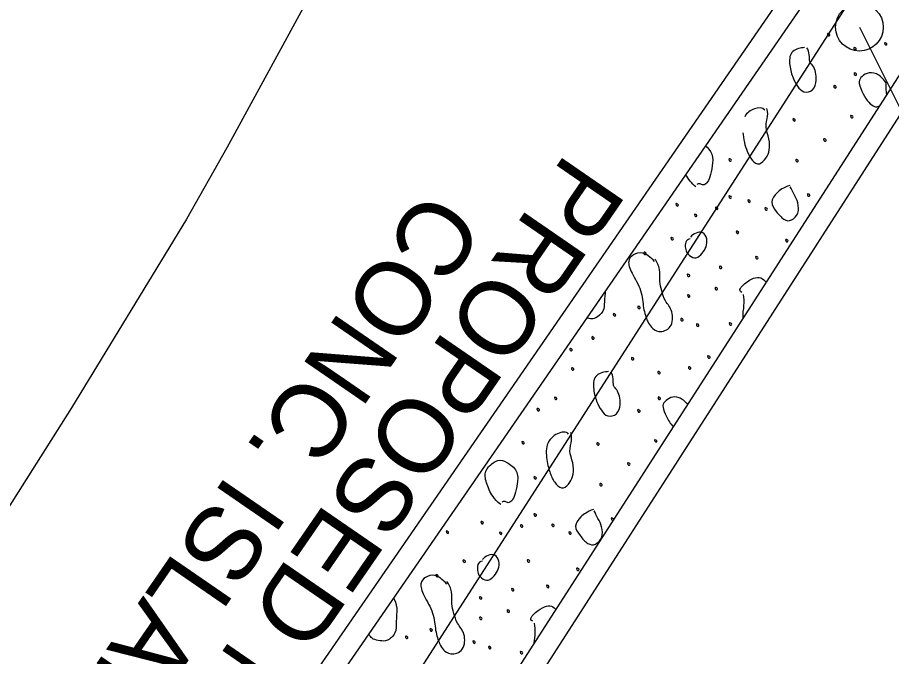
# Model space of a CAD drawing. Extents: x 1763480 to 1764420, y 711010 to 712012.
# Drawn here: x 1763800.78 to 1763830.2, y 711388.07 to 711409.59 of the extents above; entities that cross this region are included whole.
import ezdxf

# ---------------------------------------------------------------- set-up
doc = ezdxf.new("R2010")
doc.units = 0
for name, color, linetype in [('Old_Level_10', 7, 'Continuous'), ('Prop Conc Island Cover', 7, 'Continuous'), ('Prop EOT', 7, 'Continuous'), ('Prop Grid Mask', 7, 'Continuous'), ('Prop Lane Lines', 7, 'Continuous'), ('Sheet Block Revision CELL', 7, 'Continuous')]:
    doc.layers.add(name, color=color, linetype=linetype)

msp = doc.modelspace()

# ---------------------------------------------------------------- linework, layer by layer
at = {"layer": 'Old_Level_10'}
for points in [[(1763828.07, 711409.063), (1763828.044, 711409.064), (1763828.04, 711408.985), (1763828.119, 711408.957), (1763828.139, 711409.021), (1763828.104, 711409.042), (1763828.081, 711409.052), (1763828.069, 711409.056)], [(1763829.989, 711408.755), (1763829.963, 711408.755), (1763829.961, 711408.68), (1763830.039, 711408.652), (1763830.058, 711408.711), (1763830.024, 711408.736), (1763830.001, 711408.745), (1763829.988, 711408.748)], [(1763827.273, 711408.581), (1763827.161, 711408.572), (1763826.802, 711408.51), (1763826.742, 711408.056), (1763826.87, 711407.553), (1763827.038, 711407.269), (1763827.226, 711407.043), (1763827.592, 711407.107), (1763827.688, 711407.49), (1763827.655, 711407.758), (1763827.567, 711407.985), (1763827.422, 711408.088), (1763827.456, 711408.339), (1763827.396, 711408.509), (1763827.358, 711408.573)], [(1763828.956, 711408.599), (1763828.93, 711408.598), (1763828.927, 711408.524), (1763829.005, 711408.491), (1763829.025, 711408.554), (1763828.99, 711408.578), (1763828.967, 711408.587), (1763828.955, 711408.59)], [(1763828.967, 711407.735), (1763828.94, 711407.735), (1763828.937, 711407.657), (1763829.017, 711407.63), (1763829.036, 711407.692), (1763829.001, 711407.715), (1763828.978, 711407.724), (1763828.966, 711407.727)], [(1763830.021, 711407.394), (1763829.914, 711407.538), (1763829.693, 711407.748), (1763829.366, 711407.733), (1763829.154, 711407.568), (1763829.076, 711407.407), (1763829.254, 711407.007), (1763829.429, 711406.712), (1763829.649, 711406.573), (1763829.722, 711406.584), (1763829.796, 711406.613)], [(1763828.282, 711407.309), (1763828.256, 711407.309), (1763828.253, 711407.232), (1763828.332, 711407.202), (1763828.352, 711407.264), (1763828.317, 711407.288), (1763828.294, 711407.296), (1763828.281, 711407.3)], [(1763830.048, 711407.005), (1763830.035, 711407.063), (1763830.021, 711407.194), (1763830.017, 711407.323), (1763830.021, 711407.394)], [(1763825.203, 711405.711), (1763825.211, 711405.641), (1763825.241, 711405.36), (1763825.338, 711405.1), (1763825.495, 711404.754), (1763825.76, 711404.601), (1763825.997, 711404.858), (1763826.107, 711405.104), (1763826.103, 711405.512), (1763825.927, 711405.908), (1763826.069, 711406.272), (1763826.019, 711406.486), (1763826.004, 711406.529)], [(1763825.935, 711406.474), (1763825.86, 711406.566), (1763825.576, 711406.553), (1763825.332, 711406.386), (1763825.264, 711406.251)], [(1763826.905, 711406.196), (1763826.879, 711406.196), (1763826.876, 711406.119), (1763826.955, 711406.089), (1763826.975, 711406.151), (1763826.939, 711406.175), (1763826.917, 711406.184), (1763826.904, 711406.187)], [(1763828.848, 711406.299), (1763828.822, 711406.298), (1763828.82, 711406.224), (1763828.896, 711406.193), (1763828.918, 711406.254), (1763828.882, 711406.278), (1763828.86, 711406.287), (1763828.847, 711406.29)], [(1763827.942, 711405.517), (1763827.916, 711405.517), (1763827.912, 711405.44), (1763827.992, 711405.41), (1763828.012, 711405.473), (1763827.976, 711405.496), (1763827.954, 711405.504), (1763827.941, 711405.508)], [(1763823.94, 711405.272), (1763824.005, 711405.231), (1763824.206, 711404.993), (1763824.175, 711404.594), (1763824.092, 711404.192), (1763823.986, 711403.999), (1763823.859, 711403.926), (1763823.765, 711404.012), (1763823.672, 711403.989), (1763823.644, 711403.971)], [(1763824.751, 711404.841), (1763824.725, 711404.841), (1763824.722, 711404.763), (1763824.8, 711404.736), (1763824.822, 711404.798), (1763824.786, 711404.821), (1763824.764, 711404.83), (1763824.751, 711404.833)], [(1763827.003, 711404.822), (1763826.977, 711404.823), (1763826.974, 711404.745), (1763827.053, 711404.715), (1763827.073, 711404.779), (1763827.037, 711404.801), (1763827.015, 711404.81), (1763827.002, 711404.814)], [(1763823.613, 711403.887), (1763823.474, 711404.006), (1763823.361, 711404.153), (1763823.273, 711404.305)], [(1763826.777, 711403.938), (1763826.555, 711403.859), (1763826.333, 711403.703), (1763826.096, 711403.374), (1763826.313, 711403.054), (1763826.587, 711402.749), (1763826.833, 711402.726), (1763827.097, 711402.984), (1763827.067, 711403.366), (1763826.922, 711403.638), (1763826.833, 711403.811), (1763826.793, 711403.894)], [(1763824.753, 711403.592), (1763824.727, 711403.592), (1763824.724, 711403.513), (1763824.802, 711403.486), (1763824.824, 711403.548), (1763824.788, 711403.57), (1763824.765, 711403.579), (1763824.752, 711403.583)], [(1763825.388, 711403.457), (1763825.362, 711403.457), (1763825.358, 711403.381), (1763825.437, 711403.351), (1763825.458, 711403.415), (1763825.423, 711403.437), (1763825.4, 711403.446), (1763825.387, 711403.45)], [(1763827.393, 711403.66), (1763827.367, 711403.661), (1763827.364, 711403.582), (1763827.442, 711403.555), (1763827.464, 711403.616), (1763827.429, 711403.639), (1763827.406, 711403.648), (1763827.393, 711403.651)], [(1763822.967, 711403.334), (1763822.941, 711403.334), (1763822.938, 711403.257), (1763823.016, 711403.226), (1763823.037, 711403.289), (1763823.001, 711403.311), (1763822.979, 711403.32), (1763822.966, 711403.324)], [(1763824.296, 711403.22), (1763824.27, 711403.221), (1763824.269, 711403.144), (1763824.346, 711403.115), (1763824.368, 711403.175), (1763824.332, 711403.199), (1763824.309, 711403.208), (1763824.295, 711403.212)], [(1763825.963, 711403.191), (1763825.937, 711403.192), (1763825.935, 711403.113), (1763826.012, 711403.086), (1763826.034, 711403.148), (1763825.998, 711403.17), (1763825.975, 711403.179), (1763825.962, 711403.182)], [(1763823.592, 711402.976), (1763823.566, 711402.977), (1763823.563, 711402.9), (1763823.642, 711402.87), (1763823.662, 711402.931), (1763823.627, 711402.955), (1763823.604, 711402.964), (1763823.591, 711402.968)], [(1763823.43, 711402.138), (1763823.265, 711402.129), (1763823.233, 711401.766), (1763823.385, 711401.561), (1763823.631, 711401.445), (1763823.835, 711401.649), (1763823.978, 711401.856), (1763824.013, 711402.152), (1763823.859, 711402.388), (1763823.626, 711402.351), (1763823.472, 711402.247), (1763823.435, 711402.199)], [(1763824.998, 711402.409), (1763824.972, 711402.41), (1763824.969, 711402.332), (1763825.049, 711402.302), (1763825.069, 711402.364), (1763825.034, 711402.388), (1763825.01, 711402.397), (1763824.997, 711402.401)], [(1763822.798, 711402.189), (1763822.772, 711402.19), (1763822.769, 711402.113), (1763822.848, 711402.084), (1763822.869, 711402.144), (1763822.834, 711402.17), (1763822.81, 711402.178), (1763822.797, 711402.182)], [(1763826.66, 711402.128), (1763826.633, 711402.128), (1763826.628, 711402.05), (1763826.709, 711402.022), (1763826.729, 711402.085), (1763826.694, 711402.107), (1763826.672, 711402.117), (1763826.659, 711402.12)], [(1763822.229, 711401.369), (1763822.08, 711401.535), (1763821.804, 711401.72), (1763821.499, 711401.607), (1763821.302, 711401.413), (1763821.426, 711401.013), (1763821.818, 711400.389), (1763821.83, 711399.797), (1763821.997, 711399.314), (1763822.108, 711399.169), (1763822.323, 711398.96), (1763822.832, 711399.096), (1763822.866, 711399.73), (1763822.557, 711400.04), (1763822.472, 711400.393), (1763822.374, 711400.685), (1763822.431, 711401.125), (1763822.309, 711401.348), (1763822.237, 711401.454)], [(1763821.884, 711401.7), (1763821.858, 711401.699), (1763821.855, 711401.624), (1763821.933, 711401.592), (1763821.954, 711401.656), (1763821.918, 711401.679), (1763821.895, 711401.687), (1763821.883, 711401.691)], [(1763825.649, 711401.55), (1763825.623, 711401.549), (1763825.618, 711401.474), (1763825.698, 711401.444), (1763825.718, 711401.506), (1763825.683, 711401.53), (1763825.66, 711401.539), (1763825.648, 711401.542)], [(1763824.432, 711401.227), (1763824.406, 711401.226), (1763824.403, 711401.152), (1763824.482, 711401.12), (1763824.502, 711401.183), (1763824.466, 711401.207), (1763824.444, 711401.216), (1763824.431, 711401.219)], [(1763823.351, 711400.953), (1763823.325, 711400.953), (1763823.322, 711400.878), (1763823.401, 711400.848), (1763823.42, 711400.91), (1763823.385, 711400.934), (1763823.362, 711400.942), (1763823.35, 711400.946)], [(1763825.168, 711400.331), (1763825.019, 711400.394), (1763825.274, 711400.667), (1763825.567, 711400.829), (1763825.815, 711400.865), (1763825.95, 711400.716), (1763825.981, 711400.675)], [(1763824.285, 711400.508), (1763824.259, 711400.509), (1763824.254, 711400.431), (1763824.335, 711400.401), (1763824.356, 711400.465), (1763824.32, 711400.487), (1763824.297, 711400.496), (1763824.284, 711400.5)], [(1763820.567, 711400.38), (1763820.568, 711400.287), (1763820.519, 711399.997), (1763820.549, 711399.703), (1763820.212, 711399.425), (1763820.079, 711399.446), (1763819.949, 711399.466), (1763819.938, 711399.467)], [(1763823.356, 711400.263), (1763823.33, 711400.264), (1763823.328, 711400.187), (1763823.406, 711400.158), (1763823.427, 711400.218), (1763823.391, 711400.242), (1763823.368, 711400.251), (1763823.355, 711400.255)], [(1763825.206, 711399.469), (1763825.196, 711399.628), (1763825.257, 711399.887), (1763825.239, 711400.153), (1763825.225, 711400.26)], [(1763821.684, 711399.876), (1763821.658, 711399.876), (1763821.653, 711399.799), (1763821.734, 711399.769), (1763821.754, 711399.831), (1763821.719, 711399.855), (1763821.696, 711399.865), (1763821.684, 711399.868)], [(1763820.858, 711399.627), (1763820.831, 711399.627), (1763820.83, 711399.55), (1763820.908, 711399.522), (1763820.928, 711399.582), (1763820.893, 711399.607), (1763820.87, 711399.616), (1763820.858, 711399.619)], [(1763823.128, 711399.463), (1763823.103, 711399.462), (1763823.101, 711399.388), (1763823.178, 711399.356), (1763823.199, 711399.418), (1763823.164, 711399.443), (1763823.14, 711399.452), (1763823.128, 711399.455)], [(1763823.658, 711399.281), (1763823.632, 711399.281), (1763823.627, 711399.204), (1763823.707, 711399.173), (1763823.728, 711399.237), (1763823.692, 711399.26), (1763823.67, 711399.269), (1763823.657, 711399.272)], [(1763824.763, 711399.316), (1763824.737, 711399.317), (1763824.734, 711399.238), (1763824.812, 711399.211), (1763824.833, 711399.272), (1763824.798, 711399.295), (1763824.775, 711399.305), (1763824.762, 711399.309)], [(1763820.131, 711398.851), (1763820.105, 711398.851), (1763820.102, 711398.773), (1763820.18, 711398.746), (1763820.202, 711398.806), (1763820.166, 711398.829), (1763820.143, 711398.838), (1763820.13, 711398.842)], [(1763819.394, 711398.458), (1763819.368, 711398.459), (1763819.363, 711398.381), (1763819.443, 711398.351), (1763819.463, 711398.413), (1763819.428, 711398.437), (1763819.406, 711398.446), (1763819.393, 711398.449)], [(1763821.467, 711398.147), (1763821.441, 711398.147), (1763821.437, 711398.069), (1763821.516, 711398.041), (1763821.537, 711398.104), (1763821.501, 711398.125), (1763821.479, 711398.136), (1763821.466, 711398.139)], [(1763824.034, 711398.203), (1763824.008, 711398.204), (1763824.006, 711398.127), (1763824.085, 711398.097), (1763824.105, 711398.16), (1763824.069, 711398.182), (1763824.046, 711398.191), (1763824.033, 711398.195)], [(1763819.447, 711397.804), (1763819.421, 711397.804), (1763819.42, 711397.728), (1763819.497, 711397.699), (1763819.519, 711397.762), (1763819.483, 711397.784), (1763819.46, 711397.793), (1763819.446, 711397.797)], [(1763823.386, 711397.839), (1763823.36, 711397.838), (1763823.359, 711397.763), (1763823.436, 711397.735), (1763823.455, 711397.794), (1763823.421, 711397.819), (1763823.398, 711397.828), (1763823.385, 711397.831)], [(1763820.67, 711397.664), (1763820.558, 711397.655), (1763820.199, 711397.594), (1763820.139, 711397.14), (1763820.267, 711396.636), (1763820.435, 711396.352), (1763820.623, 711396.126), (1763820.989, 711396.19), (1763821.086, 711396.573), (1763821.052, 711396.842), (1763820.964, 711397.068), (1763820.819, 711397.172), (1763820.854, 711397.422), (1763820.793, 711397.592), (1763820.755, 711397.656)], [(1763822.353, 711397.682), (1763822.327, 711397.681), (1763822.325, 711397.607), (1763822.403, 711397.575), (1763822.422, 711397.638), (1763822.387, 711397.661), (1763822.364, 711397.67), (1763822.352, 711397.673)], [(1763818.055, 711396.738), (1763818.059, 711396.742), (1763818.063, 711396.747), (1763818.066, 711396.753)], [(1763818.877, 711396.811), (1763818.852, 711396.81), (1763818.851, 711396.735), (1763818.927, 711396.706), (1763818.948, 711396.767), (1763818.913, 711396.791), (1763818.889, 711396.8), (1763818.877, 711396.803)], [(1763822.364, 711396.818), (1763822.338, 711396.818), (1763822.334, 711396.74), (1763822.414, 711396.713), (1763822.433, 711396.775), (1763822.398, 711396.798), (1763822.375, 711396.807), (1763822.363, 711396.81)], [(1763823.342, 711396.567), (1763823.246, 711396.663), (1763823.05, 711396.829), (1763822.763, 711396.816), (1763822.551, 711396.651), (1763822.474, 711396.49), (1763822.619, 711396.156), (1763822.756, 711395.915), (1763822.854, 711395.808)], [(1763818.289, 711396.434), (1763818.263, 711396.433), (1763818.259, 711396.358), (1763818.339, 711396.328), (1763818.359, 711396.39), (1763818.324, 711396.414), (1763818.301, 711396.423), (1763818.288, 711396.427)], [(1763821.679, 711396.392), (1763821.653, 711396.392), (1763821.65, 711396.315), (1763821.729, 711396.286), (1763821.749, 711396.347), (1763821.714, 711396.371), (1763821.691, 711396.38), (1763821.678, 711396.383)], [(1763819.332, 711395.557), (1763819.258, 711395.65), (1763818.947, 711395.636), (1763818.533, 711395.243), (1763818.604, 711394.593), (1763818.72, 711394.182), (1763818.904, 711393.838), (1763819.157, 711393.685), (1763819.394, 711393.941), (1763819.504, 711394.187), (1763819.5, 711394.595), (1763819.324, 711394.991), (1763819.466, 711395.355), (1763819.417, 711395.569), (1763819.402, 711395.612)], [(1763817.778, 711395.318), (1763817.753, 711395.317), (1763817.75, 711395.242), (1763817.829, 711395.214), (1763817.848, 711395.273), (1763817.813, 711395.298), (1763817.79, 711395.307), (1763817.778, 711395.31)], [(1763820.302, 711395.279), (1763820.276, 711395.279), (1763820.273, 711395.202), (1763820.352, 711395.172), (1763820.372, 711395.234), (1763820.337, 711395.258), (1763820.314, 711395.267), (1763820.301, 711395.27)], [(1763822.245, 711395.382), (1763822.219, 711395.381), (1763822.217, 711395.307), (1763822.293, 711395.276), (1763822.315, 711395.337), (1763822.28, 711395.361), (1763822.257, 711395.37), (1763822.244, 711395.373)], [(1763817.047, 711393.183), (1763816.805, 711393.39), (1763816.643, 711393.681), (1763816.476, 711394.158), (1763816.597, 711394.47), (1763816.971, 711394.727), (1763817.232, 711394.644), (1763817.646, 711394.336), (1763817.609, 711393.89), (1763817.527, 711393.487), (1763817.42, 711393.295), (1763817.293, 711393.222), (1763817.199, 711393.307), (1763817.106, 711393.285), (1763817.078, 711393.266)], [(1763821.339, 711394.6), (1763821.313, 711394.6), (1763821.31, 711394.523), (1763821.389, 711394.493), (1763821.409, 711394.556), (1763821.374, 711394.579), (1763821.351, 711394.587), (1763821.338, 711394.591)], [(1763818.185, 711394.136), (1763818.159, 711394.137), (1763818.156, 711394.059), (1763818.234, 711394.032), (1763818.256, 711394.093), (1763818.22, 711394.116), (1763818.198, 711394.125), (1763818.185, 711394.129)], [(1763820.401, 711393.906), (1763820.374, 711393.906), (1763820.371, 711393.828), (1763820.45, 711393.798), (1763820.47, 711393.862), (1763820.435, 711393.884), (1763820.412, 711393.893), (1763820.4, 711393.897)], [(1763818.188, 711392.887), (1763818.161, 711392.887), (1763818.159, 711392.809), (1763818.237, 711392.781), (1763818.259, 711392.844), (1763818.222, 711392.866), (1763818.199, 711392.875), (1763818.187, 711392.878)], [(1763820.174, 711393.022), (1763819.952, 711392.942), (1763819.73, 711392.787), (1763819.493, 711392.457), (1763819.71, 711392.137), (1763819.984, 711391.832), (1763820.23, 711391.809), (1763820.494, 711392.067), (1763820.464, 711392.449), (1763820.319, 711392.722), (1763820.23, 711392.894), (1763820.19, 711392.977)], [(1763816.401, 711392.629), (1763816.375, 711392.63), (1763816.372, 711392.552), (1763816.451, 711392.522), (1763816.471, 711392.584), (1763816.436, 711392.607), (1763816.413, 711392.615), (1763816.4, 711392.619)], [(1763817.731, 711392.516), (1763817.704, 711392.516), (1763817.703, 711392.439), (1763817.781, 711392.41), (1763817.802, 711392.47), (1763817.766, 711392.495), (1763817.743, 711392.503), (1763817.73, 711392.507)], [(1763818.785, 711392.54), (1763818.759, 711392.54), (1763818.755, 711392.464), (1763818.835, 711392.434), (1763818.855, 711392.498), (1763818.82, 711392.52), (1763818.797, 711392.529), (1763818.784, 711392.533)], [(1763820.79, 711392.743), (1763820.764, 711392.744), (1763820.768, 711392.671), (1763820.815, 711392.653), (1763820.827, 711392.653)], [(1763820.858, 711392.7), (1763820.857, 711392.701), (1763820.848, 711392.709), (1763820.826, 711392.722), (1763820.803, 711392.731), (1763820.791, 711392.735)], [(1763815.232, 711392.307), (1763815.205, 711392.307), (1763815.201, 711392.23), (1763815.281, 711392.199), (1763815.301, 711392.262), (1763815.266, 711392.285), (1763815.243, 711392.294), (1763815.231, 711392.298)], [(1763817.026, 711392.272), (1763817, 711392.272), (1763816.997, 711392.195), (1763817.076, 711392.166), (1763817.096, 711392.227), (1763817.061, 711392.251), (1763817.038, 711392.26), (1763817.025, 711392.263)], [(1763819.36, 711392.274), (1763819.334, 711392.275), (1763819.332, 711392.196), (1763819.41, 711392.169), (1763819.431, 711392.231), (1763819.395, 711392.253), (1763819.372, 711392.262), (1763819.359, 711392.266)], [(1763815.797, 711391.328), (1763815.771, 711391.329), (1763815.768, 711391.252), (1763815.847, 711391.223), (1763815.868, 711391.283), (1763815.833, 711391.309), (1763815.809, 711391.317), (1763815.796, 711391.321)], [(1763816.429, 711391.277), (1763816.264, 711391.268), (1763816.233, 711390.906), (1763816.384, 711390.7), (1763816.63, 711390.584), (1763816.834, 711390.789), (1763816.977, 711390.995), (1763817.012, 711391.291), (1763816.858, 711391.527), (1763816.625, 711391.49), (1763816.471, 711391.386), (1763816.435, 711391.338)], [(1763817.96, 711391.336), (1763817.934, 711391.337), (1763817.931, 711391.259), (1763818.011, 711391.229), (1763818.031, 711391.291), (1763817.996, 711391.315), (1763817.972, 711391.324), (1763817.959, 711391.328)], [(1763819.622, 711391.055), (1763819.595, 711391.055), (1763819.59, 711390.977), (1763819.671, 711390.949), (1763819.691, 711391.012), (1763819.656, 711391.034), (1763819.634, 711391.044), (1763819.621, 711391.047)], [(1763815.228, 711390.508), (1763815.079, 711390.674), (1763814.803, 711390.859), (1763814.498, 711390.746), (1763814.301, 711390.553), (1763814.425, 711390.152), (1763814.817, 711389.528), (1763814.829, 711388.936), (1763814.996, 711388.454), (1763815.107, 711388.308), (1763815.322, 711388.099), (1763815.831, 711388.235), (1763815.865, 711388.869), (1763815.556, 711389.179), (1763815.471, 711389.532), (1763815.373, 711389.824), (1763815.43, 711390.264), (1763815.308, 711390.487), (1763815.236, 711390.593)], [(1763814.883, 711390.839), (1763814.857, 711390.838), (1763814.854, 711390.764), (1763814.932, 711390.731), (1763814.953, 711390.795), (1763814.917, 711390.818), (1763814.894, 711390.827), (1763814.882, 711390.83)], [(1763818.611, 711390.477), (1763818.585, 711390.476), (1763818.58, 711390.401), (1763818.66, 711390.371), (1763818.68, 711390.433), (1763818.645, 711390.457), (1763818.622, 711390.466), (1763818.61, 711390.469)], [(1763817.431, 711390.366), (1763817.405, 711390.365), (1763817.402, 711390.291), (1763817.481, 711390.259), (1763817.501, 711390.322), (1763817.465, 711390.346), (1763817.443, 711390.355), (1763817.43, 711390.358)], [(1763813.438, 711390.042), (1763813.476, 711389.974), (1763813.582, 711389.702), (1763813.508, 711389.236), (1763813.548, 711388.842), (1763813.211, 711388.564), (1763812.992, 711388.601), (1763812.724, 711388.636), (1763812.629, 711388.789), (1763812.617, 711388.813), (1763812.608, 711388.837)], [(1763816.35, 711390.093), (1763816.324, 711390.093), (1763816.321, 711390.017), (1763816.4, 711389.988), (1763816.419, 711390.049), (1763816.384, 711390.073), (1763816.361, 711390.081), (1763816.349, 711390.085)], [(1763817.284, 711389.648), (1763817.258, 711389.648), (1763817.253, 711389.57), (1763817.334, 711389.54), (1763817.355, 711389.604), (1763817.319, 711389.627), (1763817.296, 711389.635), (1763817.283, 711389.639)], [(1763818.13, 711389.258), (1763817.98, 711389.321), (1763818.236, 711389.594), (1763818.529, 711389.756), (1763818.759, 711389.802), (1763818.882, 711389.675), (1763818.9, 711389.654)], [(1763816.355, 711389.403), (1763816.329, 711389.403), (1763816.327, 711389.326), (1763816.405, 711389.297), (1763816.426, 711389.357), (1763816.39, 711389.382), (1763816.367, 711389.39), (1763816.354, 711389.394)], [(1763814.683, 711389.015), (1763814.657, 711389.015), (1763814.652, 711388.938), (1763814.733, 711388.908), (1763814.753, 711388.97), (1763814.718, 711388.994), (1763814.695, 711389.004), (1763814.683, 711389.007)], [(1763818.175, 711388.525), (1763818.191, 711388.638), (1763818.216, 711388.857), (1763818.201, 711389.08), (1763818.187, 711389.187)], [(1763813.857, 711388.766), (1763813.83, 711388.766), (1763813.829, 711388.689), (1763813.907, 711388.661), (1763813.927, 711388.721), (1763813.892, 711388.746), (1763813.869, 711388.755), (1763813.857, 711388.758)], [(1763816.128, 711388.602), (1763816.102, 711388.601), (1763816.1, 711388.527), (1763816.177, 711388.496), (1763816.198, 711388.557), (1763816.163, 711388.582), (1763816.139, 711388.591), (1763816.127, 711388.594)], [(1763816.657, 711388.42), (1763816.631, 711388.42), (1763816.626, 711388.343), (1763816.706, 711388.313), (1763816.727, 711388.376), (1763816.691, 711388.399), (1763816.669, 711388.408), (1763816.656, 711388.411)], [(1763817.725, 711388.243), (1763817.699, 711388.244), (1763817.696, 711388.165), (1763817.774, 711388.138), (1763817.795, 711388.199), (1763817.76, 711388.222), (1763817.737, 711388.232), (1763817.724, 711388.236)]]:
    msp.add_open_spline(points, degree=3, dxfattribs=at)
at = {"layer": 'Prop Conc Island Cover'}
for p, q in [((1763827.477, 711410.401), (1763801.351, 711372.511)), ((1763830.806, 711408.185), (1763805.942, 711369.484))]:
    msp.add_line(p, q, dxfattribs=at)
at = {"layer": 'Prop EOT'}
for p, q in [((1763811.964, 711412.813), (1763807.82, 711405.205)), ((1763807.82, 711405.205), (1763806.464, 711402.795)), ((1763806.464, 711402.795), (1763802.597, 711396.443)), ((1763802.597, 711396.443), (1763797.42, 711388.278))]:
    msp.add_line(p, q, dxfattribs=at)
at = {"layer": 'Prop Grid Mask'}
msp.add_line((1763829.123, 711409.266), (1763841.422, 711384.617), dxfattribs=at)
msp.add_circle((1763829.123, 711409.266), 0.802, dxfattribs=at)
at = {"layer": 'Prop Lane Lines'}
for p, q in [((1763826.859, 711410.827), (1763800.553, 711372.676)), ((1763805.492, 711367.396), (1763831.437, 711407.78)), ((1763806.573, 711369.079), (1763831.437, 711407.78))]:
    msp.add_line(p, q, dxfattribs=at)
msp.add_arc((1763829.123, 711409.266), 2.75, 327.2804, 147.2804, dxfattribs=at)
at = {"layer": 'Sheet Block Revision CELL'}
msp.add_line((1763783.028, 711338.906), (1763848.854, 711441.364), dxfattribs=at)

# ---------------------------------------------------------------- texts
at = {"layer": 'Prop Grid Mask'}
for s, p in [('PROPOSED MONO.', (1763819.264, 711405.087)), ('CONC. ISLAND', (1763814.497, 711403.903))]:
    msp.add_text(s, height=2.5, rotation=235.448, dxfattribs=at).set_placement(p)

doc.saveas('drawing.dxf')
